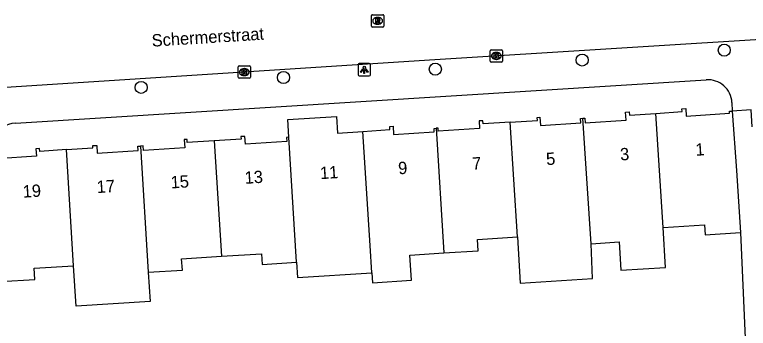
# Model space of a CAD drawing. Extents: x 159689 to 160786, y 387323 to 388339.
# Drawn here: x 160262.5 to 160322.2, y 387928.8 to 387954.3 of the extents above; entities that cross this region are included whole.
import ezdxf

# ---------------------------------------------------------------- set-up
doc = ezdxf.new("R2010")
doc.units = 0
for name, color, linetype in [('IMGEO_Boom', 7, 'Continuous'), ('IMGEO_Kolk', 7, 'Continuous'), ('IMGEO_Lichtpunt', 7, 'Continuous'), ('IMGEO_Openbare_ruimte_label', 7, 'Continuous'), ('IMGEO_Pand', 7, 'Continuous'), ('IMGEO_Pand_nummerreeks', 7, 'Continuous'), ('IMGEO_Rijbaan_lokaal_open', 7, 'Continuous'), ('IMGEO_Rioolput', 7, 'Continuous'), ('IMGEO_Voetpad_open', 7, 'Continuous')]:
    doc.layers.add(name, color=color, linetype=linetype)

msp = doc.modelspace()

# ---------------------------------------------------------------- linework, layer by layer
at = {"layer": 'IMGEO_Boom'}
for centre in [(160320.209, 387951.422), (160308.653, 387950.622), (160296.717, 387949.886), (160284.374, 387949.202), (160272.803, 387948.403)]:
    msp.add_circle(centre, 0.489, dxfattribs=at)
at = {"layer": 'IMGEO_Kolk'}
for p, q in [((160301.178, 387950.532), (160301.178, 387951.384)), ((160301.253, 387951.458), (160302.105, 387951.458)), ((160301.666, 387951.238), (160301.691, 387951.238)), ((160302.179, 387951.384), (160302.179, 387950.532)), ((160302.105, 387950.458), (160301.253, 387950.458)), ((160301.689, 387950.678), (160301.664, 387950.678)), ((160280.688, 387949.219), (160280.688, 387950.071)), ((160280.763, 387950.145), (160281.615, 387950.145)), ((160281.176, 387949.925), (160281.201, 387949.925)), ((160281.689, 387950.071), (160281.689, 387949.219)), ((160281.199, 387949.365), (160281.174, 387949.365)), ((160281.615, 387949.145), (160280.763, 387949.145))]:
    msp.add_line(p, q, dxfattribs=at)
for points in [[(160301.178, 387950.532), (160301.178, 387951.384)], [(160301.253, 387951.458), (160302.105, 387951.458)], [(160301.499, 387951.158), (160301.622, 387951.158), (160301.622, 387951.007), (160301.752, 387951.158), (160301.916, 387951.158), (160301.77, 387951.007), (160301.923, 387950.758), (160301.771, 387950.758), (160301.686, 387950.922), (160301.622, 387950.855), (160301.622, 387950.758), (160301.499, 387950.758), (160301.499, 387951.158)], [(160302.179, 387951.384), (160302.179, 387950.532)], [(160302.105, 387950.458), (160301.253, 387950.458)], [(160280.688, 387949.219), (160280.688, 387950.071)], [(160280.763, 387950.145), (160281.615, 387950.145)], [(160281.009, 387949.845), (160281.132, 387949.845), (160281.132, 387949.694), (160281.262, 387949.845), (160281.426, 387949.845), (160281.28, 387949.694), (160281.433, 387949.445), (160281.281, 387949.445), (160281.196, 387949.609), (160281.132, 387949.542), (160281.132, 387949.445), (160281.009, 387949.445), (160281.009, 387949.845)], [(160281.689, 387950.071), (160281.689, 387949.219)], [(160281.615, 387949.145), (160280.763, 387949.145)]]:
    msp.add_lwpolyline(points, dxfattribs=at)
for centre, start, end in [((160301.255, 387951.382), 91.55205, 178.44795), ((160301.255, 387951.382), 91.55205, 178.44795), ((160302.103, 387951.382), 1.55205, 88.44795), ((160302.103, 387951.382), 1.55205, 88.44795), ((160301.255, 387950.534), 181.55205, 268.44795), ((160301.255, 387950.534), 181.55205, 268.44795), ((160302.103, 387950.534), 271.55205, 358.44795), ((160302.103, 387950.534), 271.55205, 358.44795), ((160280.765, 387950.069), 91.55205, 178.44795), ((160280.765, 387950.069), 91.55205, 178.44795), ((160281.613, 387950.069), 1.55205, 88.44795), ((160281.613, 387950.069), 1.55205, 88.44795), ((160280.765, 387949.221), 181.55205, 268.44795), ((160280.765, 387949.221), 181.55205, 268.44795), ((160281.613, 387949.221), 271.55205, 358.44795), ((160281.613, 387949.221), 271.55205, 358.44795)]:
    msp.add_arc(centre, 0.0765, start, end, dxfattribs=at)
for centre, major_axis, ratio, start_param, end_param in [((160301.665, 387950.958), (-0.387, 0.002), 0.722429, 4.712389, 7.853982), ((160301.69, 387950.958), (-0.39, 0.002), 0.717154, 1.570796, 4.712389), ((160281.175, 387949.645), (-0.387, 0.002), 0.722429, 4.712389, 7.853982), ((160281.2, 387949.645), (-0.39, 0.002), 0.717154, 1.570796, 4.712389)]:
    msp.add_ellipse(centre, major_axis=major_axis, ratio=ratio, start_param=start_param, end_param=end_param, dxfattribs=at)
at = {"layer": 'IMGEO_Lichtpunt'}
for p, q in [((160290.443, 387950.238), (160290.443, 387949.431)), ((160290.443, 387950.238), (160290.443, 387949.431)), ((160291.345, 387950.333), (160290.537, 387950.333)), ((160291.345, 387950.333), (160290.537, 387950.333)), ((160291.439, 387949.431), (160291.439, 387950.238)), ((160291.439, 387949.431), (160291.439, 387950.238)), ((160290.537, 387949.337), (160291.345, 387949.337)), ((160290.537, 387949.337), (160291.345, 387949.337))]:
    msp.add_line(p, q, dxfattribs=at)
for points in [[(160290.817, 387949.902), (160290.856, 387949.874), (160290.668, 387949.612), (160290.63, 387949.639), (160290.817, 387949.902)], [(160290.919, 387949.854), (160290.966, 387949.854), (160290.966, 387949.532), (160290.919, 387949.532), (160290.919, 387949.854)], [(160291.029, 387949.874), (160291.067, 387949.901), (160291.254, 387949.639), (160291.215, 387949.611), (160291.029, 387949.874)]]:
    msp.add_lwpolyline(points, dxfattribs=at)
msp.add_circle((160290.942, 387950.036), 0.0994, dxfattribs=at)
for centre, start, end in [((160290.537, 387950.238), 90, 180), ((160290.537, 387950.238), 90, 180), ((160291.345, 387950.238), 0, 90), ((160291.345, 387950.238), 0, 90), ((160290.537, 387949.431), 180, 270), ((160290.537, 387949.431), 180, 270), ((160291.345, 387949.431), 270, 0), ((160291.345, 387949.431), 270, 360)]:
    msp.add_arc(centre, 0.0946, start, end, dxfattribs=at)
at = {"layer": 'IMGEO_Pand'}
for points in [[(160308.695, 387945.892), (160308.869, 387945.903), (160308.893, 387945.535), (160312.222, 387945.751), (160312.181, 387946.386), (160312.484, 387946.406), (160312.501, 387946.155), (160314.638, 387946.293)], [(160314.638, 387946.293), (160316.775, 387946.432), (160316.76, 387946.663), (160317.081, 387946.684), (160317.12, 387946.075), (160320.638, 387946.302), (160320.63, 387946.472), (160320.846, 387946.472)], [(160315.243, 387937.023), (160314.638, 387946.293)], [(160320.846, 387946.472), (160321.19, 387941.644), (160321.515, 387936.61)], [(160284.808, 387944.358), (160284.716, 387945.783), (160288.682, 387946.039), (160288.769, 387944.698), (160290.83, 387944.832)], [(160302.81, 387945.574), (160300.597, 387945.431), (160300.58, 387945.699), (160300.277, 387945.679), (160300.317, 387945.062), (160296.962, 387944.845), (160296.946, 387945.098), (160296.78, 387945.087)], [(160302.81, 387945.574), (160305.025, 387945.717), (160305.009, 387945.962), (160305.215, 387945.975), (160305.257, 387945.319), (160308.542, 387945.531), (160308.519, 387945.88), (160308.695, 387945.892)], [(160309.38, 387935.708), (160308.695, 387945.892)], [(160290.83, 387944.832), (160293.03, 387944.974), (160293.014, 387945.225), (160293.281, 387945.242), (160293.324, 387944.574), (160296.634, 387944.788), (160296.616, 387945.077), (160296.78, 387945.087)], [(160296.78, 387945.087), (160297.41, 387934.956)], [(160303.387, 387936.274), (160302.81, 387945.574)], [(160284.808, 387944.358), (160284.625, 387944.346), (160284.647, 387944.015), (160281.285, 387943.798), (160281.244, 387944.428), (160280.91, 387944.406), (160280.923, 387944.204), (160278.74, 387944.063)], [(160291.558, 387933.348), (160291.415, 387935.566), (160290.83, 387944.832)], [(160278.74, 387944.063), (160276.554, 387943.921), (160276.538, 387944.176), (160276.299, 387944.161), (160276.342, 387943.501), (160272.987, 387943.284), (160272.964, 387943.644), (160272.75, 387943.631)], [(160278.74, 387944.063), (160279.323, 387934.689)], [(160285.44, 387934.204), (160284.808, 387944.358)], [(160266.728, 387943.348), (160264.564, 387943.208), (160264.549, 387943.439), (160264.256, 387943.421), (160264.296, 387942.807), (160261.057, 387942.597), (160261.048, 387942.765), (160260.721, 387942.727)], [(160266.728, 387943.348), (160268.888, 387943.488), (160268.875, 387943.677), (160269.191, 387943.697), (160269.232, 387943.067), (160272.554, 387943.282), (160272.533, 387943.617), (160272.75, 387943.631)], [(160267.314, 387933.92), (160266.728, 387943.348)], [(160272.75, 387943.631), (160273.387, 387933.387)], [(160309.38, 387935.708), (160311.654, 387935.855), (160311.811, 387933.553), (160315.416, 387933.787), (160315.243, 387937.023)], [(160315.243, 387937.023), (160318.592, 387937.24), (160318.645, 387936.425), (160321.515, 387936.61)], [(160297.41, 387934.956), (160300.201, 387935.136), (160300.141, 387936.064), (160303.387, 387936.274)], [(160303.387, 387936.274), (160303.62, 387932.507), (160309.504, 387932.888), (160309.38, 387935.708)], [(160279.323, 387934.689), (160282.578, 387934.9), (160282.635, 387934.022), (160285.44, 387934.204)], [(160291.558, 387933.348), (160291.61, 387932.544), (160294.778, 387932.749), (160294.648, 387934.777), (160297.41, 387934.956)], [(160273.387, 387933.387), (160276.155, 387933.566), (160276.096, 387934.48), (160279.323, 387934.689)], [(160261.374, 387932.63), (160264.17, 387932.811), (160264.112, 387933.713), (160267.314, 387933.92)], [(160273.387, 387933.387), (160273.54, 387931.02), (160267.527, 387930.631), (160267.314, 387933.92)], [(160285.44, 387934.204), (160285.517, 387932.958), (160291.558, 387933.348)]]:
    msp.add_lwpolyline(points, dxfattribs=at)
at = {"layer": 'IMGEO_Rijbaan_lokaal_open'}
msp.add_lwpolyline([(160325.784, 387952.464), (160296.673, 387950.647), (160259.251, 387948.226)], dxfattribs=at)
at = {"layer": 'IMGEO_Rioolput'}
for p, q in [((160291.526, 387953.379), (160291.526, 387954.231)), ((160291.601, 387954.305), (160292.453, 387954.305)), ((160292.014, 387954.085), (160292.039, 387954.085)), ((160292.527, 387954.231), (160292.527, 387953.379)), ((160292.037, 387953.525), (160292.012, 387953.525)), ((160292.453, 387953.305), (160291.601, 387953.305))]:
    msp.add_line(p, q, dxfattribs=at)
for points in [[(160291.526, 387953.379), (160291.526, 387954.231)], [(160291.601, 387954.305), (160292.453, 387954.305)], [(160292.115, 387954.003), (160291.863, 387954.005), (160291.863, 387953.605)], [(160292.527, 387954.231), (160292.527, 387953.379)], [(160291.863, 387953.605), (160291.987, 387953.605), (160291.987, 387953.767), (160291.998, 387953.767)], [(160292.041, 387953.924), (160291.987, 387953.924), (160291.987, 387953.843)], [(160291.987, 387953.843), (160292.039, 387953.843)], [(160292.045, 387953.738), (160292.116, 387953.605), (160292.256, 387953.605), (160292.191, 387953.731)], [(160292.453, 387953.305), (160291.601, 387953.305)]]:
    msp.add_lwpolyline(points, dxfattribs=at)
for centre, radius, start, end in [((160291.603, 387954.229), 0.0765, 91.55205, 178.44795), ((160291.603, 387954.229), 0.0765, 91.55205, 178.44795), ((160292.114, 387953.893), 0.109, 350.36119, 89.41601), ((160292.451, 387954.229), 0.0765, 1.55205, 88.44795), ((160292.451, 387954.229), 0.0765, 1.55205, 88.44795), ((160291.603, 387953.381), 0.0765, 181.55205, 268.44795), ((160291.603, 387953.381), 0.0765, 181.55205, 268.44795), ((160291.997, 387953.714), 0.0533, 26.02933, 88.69889), ((160292.023, 387954.032), 0.19, 274.7715, 282.96867), ((160292.047, 387953.828), 0.0964, 77.00612, 93.18647), ((160292.061, 387953.885), 0.0378, 276.66336, 79.67722), ((160292.112, 387953.893), 0.112, 277.58423, 350.98172), ((160292.096, 387953.678), 0.108, 29.51342, 73.79051), ((160292.451, 387953.381), 0.0765, 271.55205, 358.44795), ((160292.451, 387953.381), 0.0765, 271.55205, 358.44795)]:
    msp.add_arc(centre, radius, start, end, dxfattribs=at)
for centre, major_axis, ratio, start_param, end_param in [((160292.013, 387953.805), (-0.387, 0.002), 0.722429, 4.712389, 7.853982), ((160292.038, 387953.805), (-0.39, 0.002), 0.717154, 1.570796, 4.712389)]:
    msp.add_ellipse(centre, major_axis=major_axis, ratio=ratio, start_param=start_param, end_param=end_param, dxfattribs=at)
at = {"layer": 'IMGEO_Voetpad_open'}
for points in [[(160262.597, 387945.497), (160318.74, 387949.02)], [(160320.831, 387947.181), (160320.846, 387946.472)], [(160322.469, 387945.204), (160322.403, 387946.57), (160320.846, 387946.472)], [(160321.515, 387936.61), (160321.98, 387926.2), (160320.683, 387926.142)]]:
    msp.add_lwpolyline(points, dxfattribs=at)
for centre, radius, start, end in [((160318.868, 387947.057), 1.967, 3.61646, 93.72135), ((160262.691, 387943.408), 2.091, 92.58053, 156.04214)]:
    msp.add_arc(centre, radius, start, end, dxfattribs=at)

# ---------------------------------------------------------------- texts
at = {"layer": 'IMGEO_Openbare_ruimte_label'}
msp.add_text('Schermerstraat', height=1, rotation=3.61207, dxfattribs=at).set_placement((160273.691, 387951.705))
at = {"layer": 'IMGEO_Pand_nummerreeks'}
for s, rotation, p in [('1', 3.55962, (160317.894, 387942.845)), ('3', 3.55962, (160311.767, 387942.464)), ('7', 3.55962, (160299.742, 387941.716)), ('5', 3.55962, (160305.755, 387942.09)), ('9', 3.55807, (160293.728, 387941.342)), ('13', 3.55962, (160281.245, 387940.567)), ('11', 3.55807, (160287.371, 387940.947)), ('17', 3.55807, (160269.22, 387939.817)), ('15', 3.55962, (160275.232, 387940.193)), ('19', 3.55962, (160263.207, 387939.444))]:
    msp.add_text(s, height=1, rotation=rotation, dxfattribs=at).set_placement(p)

doc.saveas('drawing.dxf')
